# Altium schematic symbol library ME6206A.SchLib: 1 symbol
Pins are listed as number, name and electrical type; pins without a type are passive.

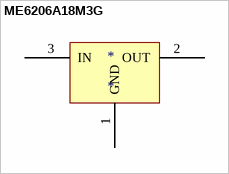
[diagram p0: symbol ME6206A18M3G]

## ME6206A18M3G
designator *
pins: 1 GND, 2 OUT, 3 IN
